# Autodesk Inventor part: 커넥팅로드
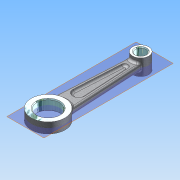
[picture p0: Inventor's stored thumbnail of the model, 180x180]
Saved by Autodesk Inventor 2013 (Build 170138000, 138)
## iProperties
Manager: KYOUNG IL JANG
Company: 한국ATC센터
Created: 2012-10
Part Number: 커넥팅로드
Document SubType Name: Modeling
Density: 1 g/cm^3
Checked By: KYOUNG IL JANG
Vendor: CBT Solutions
Designer: KYOUNG IL JANG
Material: 일반
Author: KYOUNG IL JANG
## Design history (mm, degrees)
sketch "스케치1"
  geometry: L1 (-19.879, 82.758)-(-19.879, 197.758); L2 (-27.379, 191.144)-(-32.379, 99.633); L3 (-12.379, 191.144)-(-7.379, 99.633); C1 r 14 at (-19.879, 82.758); C2 r 6.5 at (-19.879, 197.758); A1 r 19 centre (-19.879, 82.758) between (-20.11, 101.757) and (-19.649, 63.76) reference; A2 r 21 centre (-19.879, 82.758) between (-32.379, 99.633) and (-7.379, 99.633); A3 r 10 centre (-19.879, 197.758) between (-27.379, 191.144) and (-12.379, 191.144); 1 further point
  constraints: 6 end point, 4 centre point, 4 coincident, 4 point on circle, 2 horizontal alignment, 1 equal length, 1 vertical
  dimensions: "d0" = 28 diameter of C1; "d1" = 42 diameter of A2; "d4" = 115 distance of L1.end C1.centre; "d5" = 20 diameter of A3; "d6" = 13 diameter of C2; "d7" = 25 distance of L3.end L2.end; "d8" = 15 distance of L3.start L2.start
  node "참조1"
extrude "돌출1" new body sketch "스케치1" stored distance "d2" = 13; taper "d3" = 0 deg
extrude "돌출2" join sketch "스케치1" stored distance "d9" = 20; taper "d10" = 0 deg
extrude "돌출3" join sketch "스케치1" stored distance "d11" = 8; taper "d12" = 0 deg
sketch "스케치2"
  geometry: L1 (7.379, 99.633)-(12.379, 191.144) reference; L2 (27.379, 191.144)-(32.379, 99.633) reference; L3 (27.197, 121.158)-(24.092, 177.989); L4 (15.667, 177.989)-(12.561, 121.158); A1 r 21 centre (19.879, 82.758) between (7.379, 99.633) and (32.379, 99.633) reference; A2 r 7.329 centre (19.879, 120.758) between (12.561, 121.158) and (27.197, 121.158); A3 r 4.219 centre (19.879, 177.758) between (24.092, 177.989) and (15.667, 177.989); A4 r 10 centre (19.879, 197.758) between (12.379, 191.144) and (27.379, 191.144) reference; 2 further points
  constraints: 4 end point, 4 point on circle, 4 tangent, 2 centre point, 2 parallel, 1 coincident, 3 other
  dimensions: "d16" = 38 distance of A2.centre A1.centre; "d17" = 4 distance between parallel lines of L2 L3; "d18" = 4 distance between parallel lines of L4 L1; "d25" = 20 distance of A3.centre A4.centre
extrude "돌출4" cut sketch "스케치2" distance "d19" = 5; taper "d20" = 0 deg
fillet "모깎기1" dims "d21" = 2
fillet "모깎기2" dims "d22" = 3
fillet "모깎기3" dims "d23" = 3
chamfer "모따기1" distance "d26" = 1; stored, may be unused: second distance "d27" = 2, angle "d28" = 45 deg
chamfer "모따기2" distance "d29" = 1; stored, may be unused: second distance "d30" = 2, angle "d31" = 45 deg
node "작업 평면1"
node "솔리드1"
mirror "대칭1"
other parameters: "d13" = 5, "d14" = 5
